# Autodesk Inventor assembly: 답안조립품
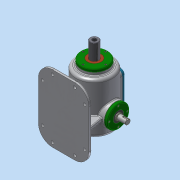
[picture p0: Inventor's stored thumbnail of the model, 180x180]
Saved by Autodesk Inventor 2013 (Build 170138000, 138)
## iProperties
Created: 2019-10
Part Number: 답안조립품
Document SubType Name: Assembly
Designer: dgall
Mass: 7821.86 g
Surface Area: 4928.07 cm^2
Volume: 2176.15 cm^3
Density: 3.59435 g/cm^3
Author: dgall
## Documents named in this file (17)
- C:\Users\dgall\Desktop\391004V1035\답안조립품.iam
- C:\Users\dgall\Desktop\391004V1035\본체.ipt
- C:\Users\dgall\Desktop\391004V1035\개스킷 B.ipt
- C:\Users\dgall\Desktop\391004V1035\베어링 6205.ipt
- 베어링 6205.ipt
- C:\Users\dgall\Desktop\391004V1035\볼트 M4x0.7.ipt
- C:\Users\dgall\Desktop\391004V1035\오일 실 25 38 8.ipt
- C:\Users\dgall\Desktop\391004V1035\축 커버.ipt
- C:\Users\dgall\Desktop\391004V1035\고정플레이트.ipt
- C:\Users\dgall\Desktop\391004V1035\상부커버.ipt
- C:\Users\dgall\Desktop\391004V1035\육각머리볼트 M4.ipt
- C:\Users\dgall\Desktop\391004V1035\가변스프링.ipt
- C:\Users\dgall\Desktop\391004V1035\개스킷 A.ipt
- C:\Users\dgall\Desktop\391004V1035\부시.ipt
- C:\Users\dgall\Desktop\391004V1035\슬라이드 커버.ipt
- C:\Users\dgall\Desktop\391004V1035\슬라이드.ipt
- C:\Users\dgall\Desktop\391004V1035\편심축.ipt
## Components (17 placed, 5 different names)
1. 개스킷 B:1
2. M4x0.7:1
3. M4x0.7:2
4. M4x0.7:3
5. M4x0.7:4
6. 개스킷 B:2
7. M4x0.7:5
8. M4x0.7:6
9. M4x0.7:7
10. M4x0.7:8
11. 고정플레이트:1 — 플러쉬:1
12. 가변스프링:1
13. 개스킷 A:1
14. M4x0.7:9
15. M4x0.7:10
16. M4x0.7:11
17. M4x0.7:12
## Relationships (1: Flush 1)
- 플러쉬:1 [Flush]: 고정플레이트:1
